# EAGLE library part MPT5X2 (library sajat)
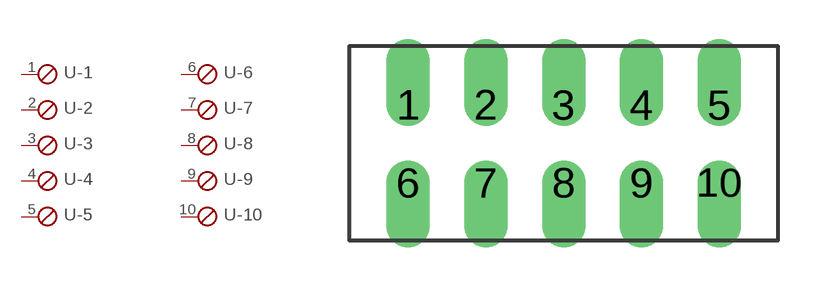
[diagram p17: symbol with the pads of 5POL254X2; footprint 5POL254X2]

Designator prefix -; gates -1=SKB -2=SKB -3=SKB -4=SKB -5=SKB -6=SKB -7=SKB -8=SKB -9=SKB -10=SKB

## MPT5X2  [5POL254X2]
1  -1:1  pas
2  -2:1  pas
3  -3:1  pas
4  -4:1  pas
5  -5:1  pas
6  -6:1  pas
7  -7:1  pas
8  -8:1  pas
9  -9:1  pas
10  -10:1  pas

## Footprint 5POL254X2 (pad centres in mm)
drill 0.3 pad 1.422 offset: 1 -5.08,1.27; 2 -2.54,1.27; 3 0,1.27; 4 2.54,1.27; 5 5.08,1.27; 6 -5.08,-1.27; 7 -2.54,-1.27; 8 0,-1.27; 9 2.54,-1.27; 10 5.08,-1.27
